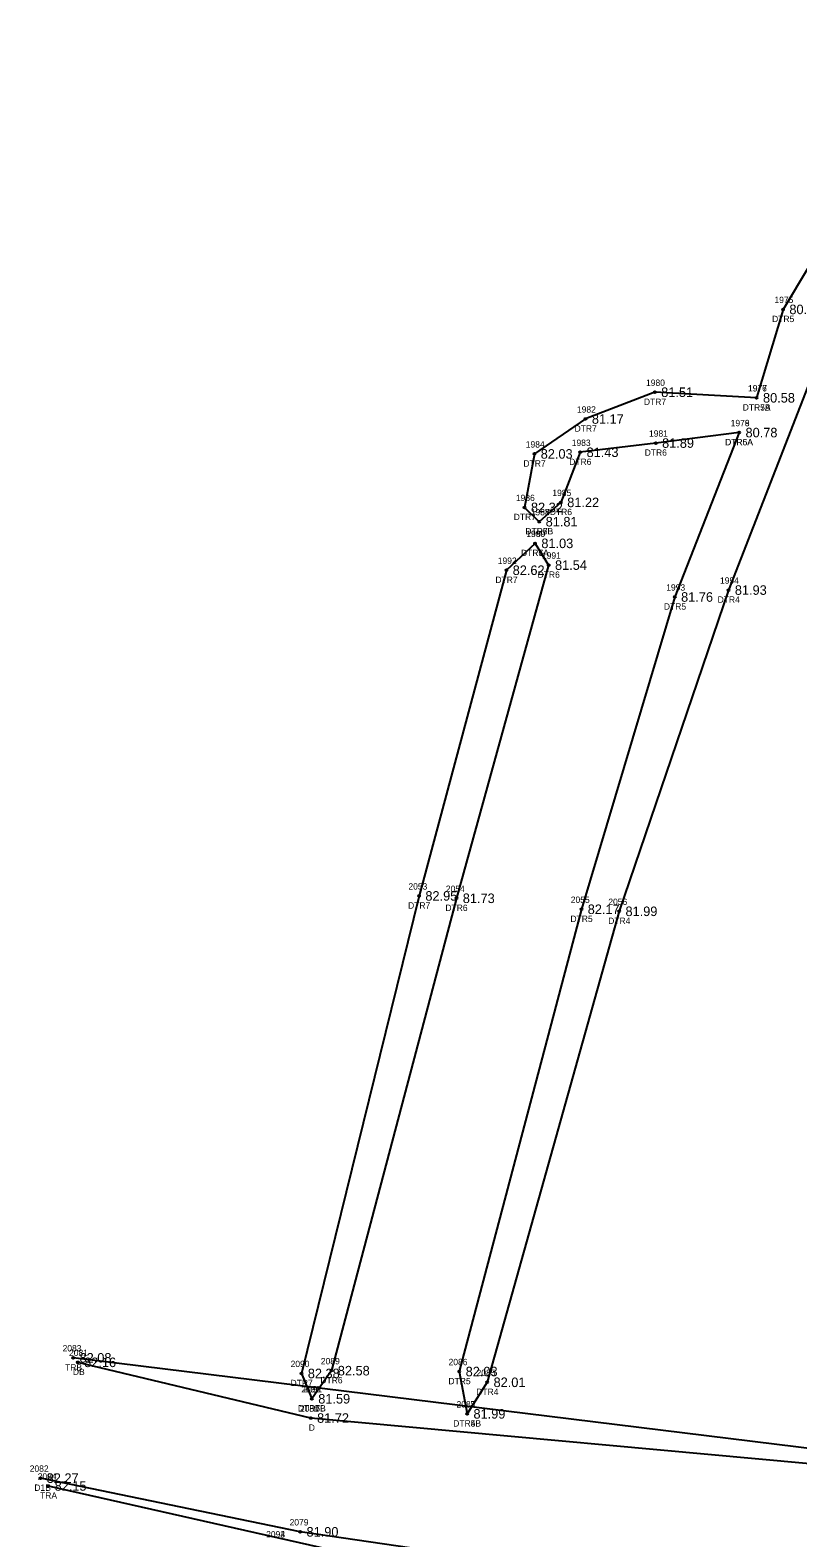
# Model space of a CAD drawing. Extents: x 2139392 to 2143384, y 505395 to 510520.
# Drawn here: x 2140403.8 to 2140524.6, y 507696.5 to 507933.9 of the extents above; entities that cross this region are included whole.
import ezdxf

# ---------------------------------------------------------------- set-up
doc = ezdxf.new("R2010")
doc.units = 0
for name, color, linetype in [('RD_EX_Driveway', 7, 'Continuous'), ('RD_EX_Driveway_txCode', 7, 'Continuous'), ('RD_EX_H2O', 7, 'Continuous'), ('RD_EX_H2O_txCode', 7, 'Continuous'), ('RD_EX_TX_Driveway_ELEV', 7, 'Continuous'), ('RD_EX_TX_H2O_ELEV', 7, 'Continuous'), ('RD_EX_TX_VEG_ELEV', 7, 'Continuous'), ('RD_EX_VEG', 7, 'Continuous'), ('RD_EX_VEG_txCode', 7, 'Continuous'), ('RD_SMD_Locator', 7, 'Continuous')]:
    doc.layers.add(name, color=color, linetype=linetype)

msp = doc.modelspace()

# ---------------------------------------------------------------- linework, layer by layer
at = {"layer": 'RD_EX_Driveway'}
for points in [[(2140559.74, 507699.59), (2140540.26, 507698.69), (2140533.99, 507707.51), (2140447.99, 507715.4), (2140411.34, 507724.17)], [(2140559.81, 507681.93), (2140539.92, 507683.79), (2140446.33, 507697.49), (2140405.44, 507705.94)]]:
    msp.add_lwpolyline(points, dxfattribs=at)
at = {"layer": 'RD_EX_H2O'}
for points in [[(2140534.15, 507909.65), (2140522.31, 507889.92), (2140518.16, 507876)], [(2140533.24, 507895.57), (2140531.72, 507893.75), (2140530.46, 507888.72), (2140513.73, 507845.74), (2140496.52, 507795.17), (2140475.76, 507721.03), (2140472.6, 507716.06)], [(2140518.16, 507876), (2140502.14, 507876.88), (2140491.23, 507872.67), (2140483.18, 507867.17), (2140481.64, 507858.75), (2140483.96, 507856.5)], [(2140515.41, 507870.53), (2140505.27, 507844.65), (2140490.58, 507795.49), (2140471.37, 507722.72), (2140472.6, 507716.06)], [(2140515.41, 507870.53), (2140502.28, 507868.88), (2140490.4, 507867.43), (2140487.35, 507859.54), (2140483.96, 507856.5)], [(2140483.28, 507853.09), (2140478.77, 507848.86), (2140465.03, 507797.59), (2140446.53, 507722.42), (2140448.17, 507718.43)], [(2140483.28, 507853.09), (2140485.43, 507849.67), (2140470.92, 507797.22), (2140451.25, 507722.86), (2140448.17, 507718.43)]]:
    msp.add_lwpolyline(points, dxfattribs=at)
at = {"layer": 'RD_EX_VEG'}
for points in [[(2140900.08, 509397.36), (2141021.29, 509326.2), (2140852.61, 508865.26), (2140689.34, 508413.46), (2140624.53, 508226.48), (2140606.41, 508171.78), (2140591.23, 508116.67), (2140558.82, 507962.77), (2140538.78, 507709.07), (2140410.61, 507724.88)], [(2140406.69, 507704.71), (2140540.94, 507674.41), (2140569.48, 507207.83), (2140538.65, 507191.93)]]:
    msp.add_lwpolyline(points, dxfattribs=at)
at = {"layer": 'RD_SMD_Locator'}
for centre in [(2140522.31, 507889.92), (2140502.14, 507876.88), (2140518.16, 507876), (2140518.16, 507876), (2140491.23, 507872.67), (2140515.41, 507870.53), (2140515.41, 507870.53), (2140490.4, 507867.43), (2140502.28, 507868.88), (2140483.18, 507867.17), (2140481.64, 507858.75), (2140487.35, 507859.54), (2140483.96, 507856.5), (2140483.96, 507856.5), (2140483.28, 507853.09), (2140483.28, 507853.09), (2140478.77, 507848.86), (2140485.43, 507849.67), (2140505.27, 507844.65), (2140513.73, 507845.74), (2140465.03, 507797.59), (2140470.92, 507797.22), (2140490.58, 507795.49), (2140496.52, 507795.17), (2140410.61, 507724.88), (2140411.34, 507724.17), (2140451.25, 507722.86), (2140471.37, 507722.72), (2140446.53, 507722.42), (2140475.76, 507721.03), (2140448.17, 507718.43), (2140448.17, 507718.43), (2140447.99, 507715.4), (2140472.6, 507716.06), (2140472.6, 507716.06), (2140405.44, 507705.94), (2140406.69, 507704.71), (2140446.33, 507697.49)]:
    msp.add_circle(centre, 0.15, dxfattribs=at)

# ---------------------------------------------------------------- texts
at = {"layer": 'RD_EX_Driveway_txCode'}
for s, p in [('2081', (2140409.95, 507725.17)), ('DB', (2140410.56, 507722.17)), ('2080', (2140446.28, 507716.4)), ('D', (2140447.68, 507713.4)), ('2082', (2140403.77, 507706.94)), ('D1B', (2140404.5, 507703.94)), ('2079', (2140444.66, 507698.49))]:
    msp.add_text(s, height=1, dxfattribs=at).set_placement(p)
at = {"layer": 'RD_EX_H2O_txCode'}
for s, p in [('1975', (2140520.96, 507890.92)), ('DTR5', (2140520.59, 507887.92)), ('1980', (2140500.75, 507877.88)), ('1976', (2140516.79, 507877)), ('1977', (2140516.82, 507877)), ('1982', (2140489.88, 507873.67)), ('DTR7', (2140500.42, 507874.88)), ('DTR7A', (2140515.96, 507874)), ('DTR5B', (2140515.97, 507874)), ('1978', (2140514.07, 507871.53)), ('1979', (2140514.07, 507871.53)), ('DTR7', (2140489.51, 507870.67)), ('1981', (2140501.22, 507869.88)), ('1984', (2140481.83, 507868.17)), ('1983', (2140489.06, 507868.43)), ('DTR6', (2140500.54, 507866.88)), ('DTR6A', (2140513.18, 507868.53)), ('DTR5A', (2140513.21, 507868.53)), ('DTR7', (2140481.46, 507865.17)), ('DTR6', (2140488.66, 507865.43)), ('1986', (2140480.27, 507859.75)), ('1985', (2140486.01, 507860.54)), ('1987', (2140482.61, 507857.5)), ('1988', (2140482.61, 507857.5)), ('DTR6', (2140485.61, 507857.54)), ('DTR7', (2140479.93, 507856.75)), ('DTR6B', (2140481.75, 507854.5)), ('DTR7B', (2140481.77, 507854.5)), ('1990', (2140481.9, 507854.09)), ('1989', (2140481.94, 507854.09)), ('1992', (2140477.42, 507849.86)), ('DTR6A', (2140481.06, 507851.09)), ('DTR7A', (2140481.08, 507851.09)), ('1991', (2140484.37, 507850.67)), ('DTR6', (2140483.69, 507847.67)), ('DTR7', (2140477.05, 507846.86)), ('1993', (2140503.93, 507845.65)), ('1994', (2140512.39, 507846.74)), ('DTR4', (2140512.02, 507843.74)), ('DTR5', (2140503.56, 507842.65)), ('2053', (2140463.36, 507798.59)), ('2054', (2140469.25, 507798.22)), ('DTR7', (2140463.31, 507795.59)), ('DTR6', (2140469.18, 507795.22)), ('2055', (2140488.91, 507796.49)), ('2056', (2140494.82, 507796.17)), ('DTR5', (2140488.86, 507793.49)), ('DTR4', (2140494.8, 507793.17)), ('2090', (2140444.82, 507723.42)), ('2089', (2140449.58, 507723.86)), ('2086', (2140469.68, 507723.72)), ('2085', (2140474.09, 507722.03)), ('DTR7', (2140444.81, 507720.42)), ('2092', (2140446.5, 507719.43)), ('2091', (2140446.79, 507719.43)), ('DTR6', (2140449.51, 507720.86)), ('DTR5', (2140469.66, 507720.72)), ('2087', (2140470.93, 507717.06)), ('2088', (2140470.93, 507717.06)), ('DTR4', (2140474.04, 507719.03)), ('DTR6B', (2140445.96, 507716.43)), ('DTR7B', (2140445.98, 507716.43)), ('DTR4B', (2140470.41, 507714.06)), ('DTR5B', (2140470.41, 507714.06)), ('2093', (2140440.97, 507696.6)), ('2094', (2140440.97, 507696.6))]:
    msp.add_text(s, height=1, dxfattribs=at).set_placement(p)
at = {"layer": 'RD_EX_TX_Driveway_ELEV'}
for s, p in [('82.16', (2140412.34, 507723.42)), ('81.72', (2140448.99, 507714.65)), ('82.27', (2140406.44, 507705.19)), ('81.90', (2140447.33, 507696.74))]:
    msp.add_text(s, height=1.5, dxfattribs=at).set_placement(p)
at = {"layer": 'RD_EX_TX_H2O_ELEV'}
for s, p in [('80.54', (2140523.31, 507889.17)), ('81.51', (2140503.14, 507876.13)), ('80.58', (2140519.16, 507875.25)), ('80.58', (2140519.16, 507875.25)), ('81.17', (2140492.23, 507871.92)), ('80.78', (2140516.41, 507869.78)), ('80.78', (2140516.41, 507869.78)), ('82.03', (2140484.18, 507866.42)), ('81.43', (2140491.4, 507866.68)), ('81.89', (2140503.28, 507868.13)), ('81.22', (2140488.35, 507858.79)), ('82.32', (2140482.64, 507858)), ('81.81', (2140484.96, 507855.75)), ('81.81', (2140484.96, 507855.75)), ('81.03', (2140484.28, 507852.34)), ('81.03', (2140484.28, 507852.34)), ('82.62', (2140479.77, 507848.11)), ('81.54', (2140486.43, 507848.92)), ('81.93', (2140514.73, 507844.99)), ('81.76', (2140506.27, 507843.9)), ('82.95', (2140466.03, 507796.84)), ('81.73', (2140471.92, 507796.47)), ('82.17', (2140491.58, 507794.74)), ('81.99', (2140497.52, 507794.42)), ('82.38', (2140447.53, 507721.67)), ('82.58', (2140452.25, 507722.11)), ('82.03', (2140472.37, 507721.97)), ('82.01', (2140476.76, 507720.28)), ('81.59', (2140449.17, 507717.68)), ('81.59', (2140449.17, 507717.68)), ('81.99', (2140473.6, 507715.31)), ('81.99', (2140473.6, 507715.31))]:
    msp.add_text(s, height=1.5, dxfattribs=at).set_placement(p)
at = {"layer": 'RD_EX_TX_VEG_ELEV'}
for s, p in [('82.08', (2140411.61, 507724.13)), ('82.15', (2140407.69, 507703.96))]:
    msp.add_text(s, height=1.5, dxfattribs=at).set_placement(p)
at = {"layer": 'RD_EX_VEG_txCode'}
for s, p in [('2083', (2140408.94, 507725.88)), ('TRB', (2140409.34, 507722.88)), ('2084', (2140405.02, 507705.71)), ('TRA', (2140405.4, 507702.71))]:
    msp.add_text(s, height=1, dxfattribs=at).set_placement(p)

doc.saveas('drawing.dxf')
